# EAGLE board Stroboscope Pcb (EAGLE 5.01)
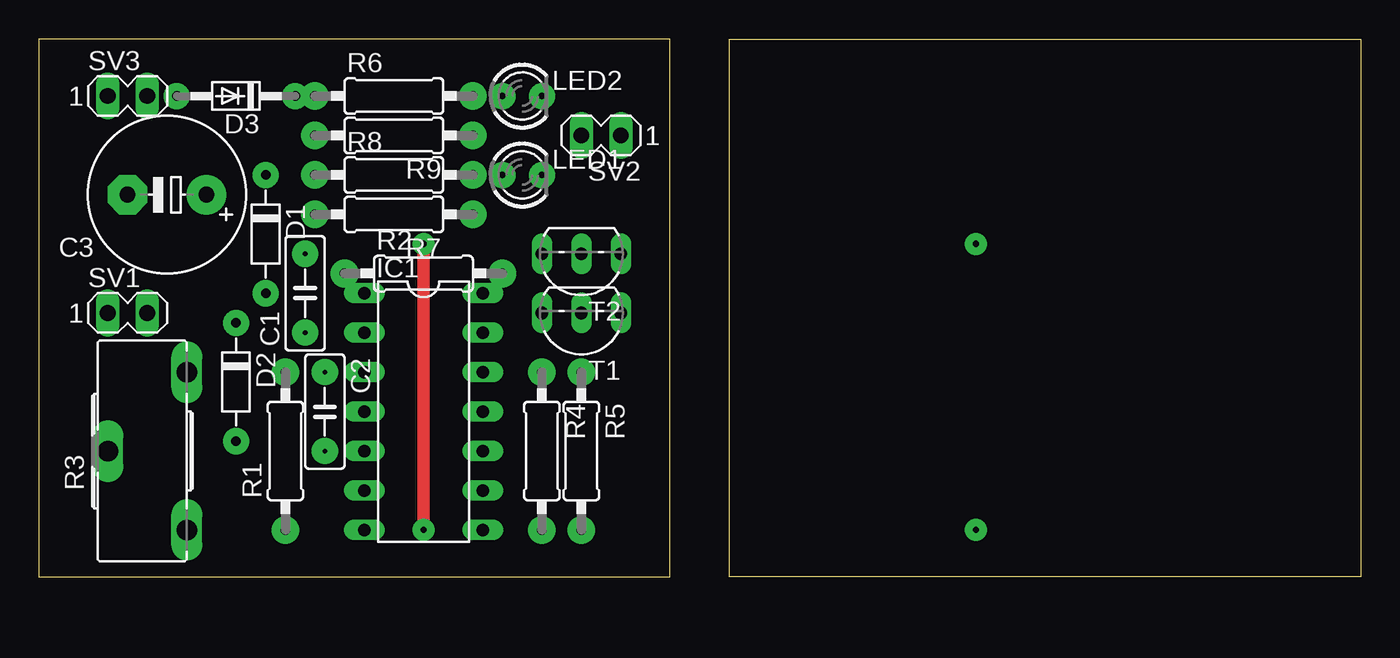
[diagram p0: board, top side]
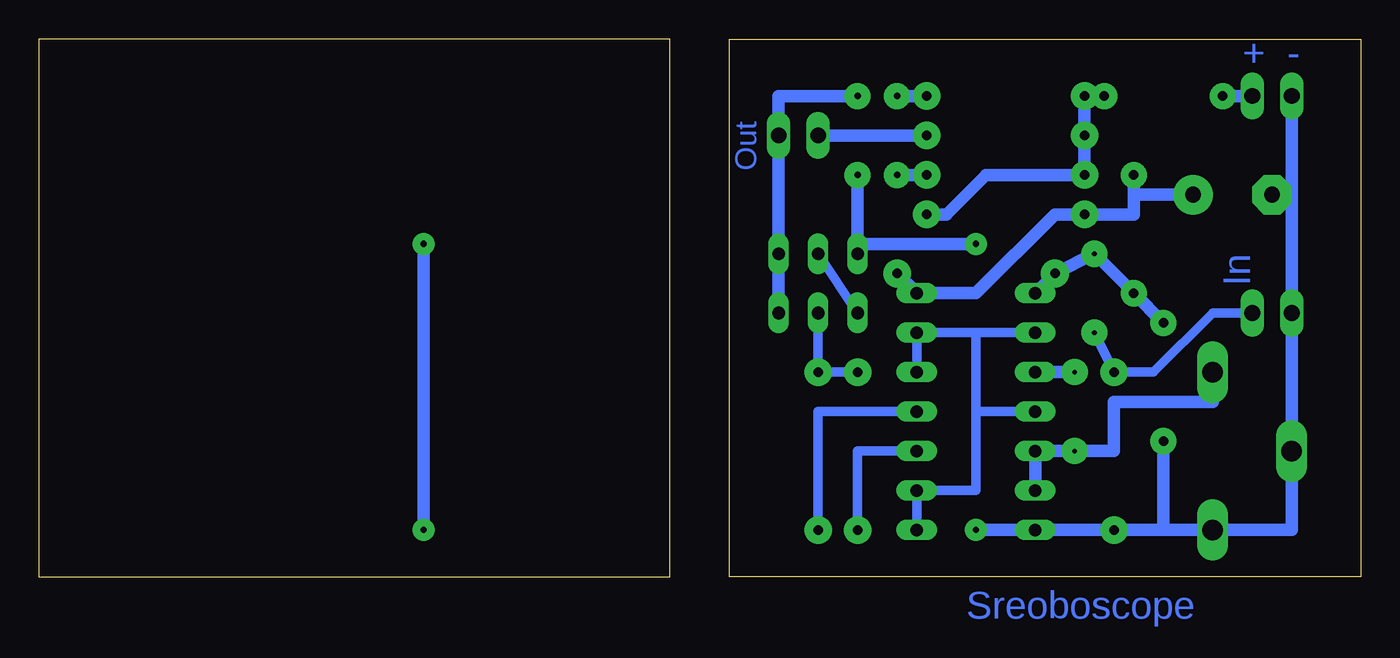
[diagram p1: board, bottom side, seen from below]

Size 85.08 x 34.59 mm. Coordinates in mm from the lower left corner, seen from the top.
Outline: 0,0 40.62,0 40.62,34.59 0,34.59 0,0
Outline: 85.08,0 44.46,0 44.46,34.59 85.08,34.59 85.08,0
Copper layers (1*16): Top 0.035mm / dielectric 1.5mm / Bottom 0.035mm
Design rules "default": minimum track width 10mil, minimum drill 24mil, track to track 8mil, track to pad 8mil, pad to pad 8mil, via to via 8mil, smd to smd 8mil, copper to edge 40mil, drill to drill 8mil, minimum pad ring 10mil, minimum via ring 8mil, stop-mask expansion 4mil, vias tented up to drill 0mil, thermal gap 10mil

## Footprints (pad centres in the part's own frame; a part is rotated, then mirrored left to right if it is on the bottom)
C050-025X075 = drill 0.305 pad 1.676 round: P$1 -2.54,0; P$2 2.54,0
E5-10,5 = drill 1.016 pad 2.54 round: + -2.54,0 | drill 1.016 pad 2.54 octagon: - 2.54,0
D-7,5/R = drill 0.61 pad 1.676 round: A 3.81,0; C -3.81,0
DO34-7/R = drill 0.61 pad 1.676 round: A 3.81,0; C -3.81,0
DIL14 = drill 0.813 long: 1 -7.62,-3.81; 2 -5.08,-3.81; 3 -2.54,-3.81; 4 0,-3.81; 5 2.54,-3.81; 6 5.08,-3.81; 7 7.62,-3.81; 8 7.62,3.81; 9 5.08,3.81; 10 2.54,3.81; 11 0,3.81; 12 -2.54,3.81; 13 -5.08,3.81; 14 -7.62,3.81
LED3MM = drill 0.406 pad 1.676 round: A -1.27,0; K 1.27,0
0207/10 = drill 0.61 pad 1.778 round: 1 -5.08,0; 2 5.08,0
CA14H = drill 1.321 long: A -5.08,0; E 5.08,0; S 0,5.08
MA2-1 = drill 1.016 long: 1 0,0; 2 2.54,0
TO92- = drill 0.813 long: 1 2.54,-1.27; 2 0,-1.27; 3 -2.54,-1.27

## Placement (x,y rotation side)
C1  100p  [C050-025X075]  17.14,18.25 90 top
C2  15n  [C050-025X075]  18.41,10.63 270 top
C3  [E5-10,5]  8.25,24.6 180 top
D1  1N4148-34/7-R  [D-7,5/R]  14.6,22.06 270 top
D2  1N4148-34/7-R  [D-7,5/R]  12.7,12.54 270 top
D3  [DO34-7/R]  12.7,30.95 180 top
IC1  4011N  [DIL14]  24.76,10.63 270 top
LED1  [LED3MM]  31.11,25.87 0 top
LED2  [LED3MM]  31.11,30.95 0 top
R1  1K  [0207/10]  15.87,8.09 90 top
R2  10M  [0207/10]  24.76,19.52 0 top
R3  47K  [CA14H]  9.52,8.09 90 top
R4  2,2K  [0207/10]  32.38,8.09 270 top
R5  2,2K  [0207/10]  34.92,8.09 270 top
R6  680  [0207/10]  22.86,30.95 0 top
R7  120  [0207/10]  22.86,23.33 180 top
R8  680  [0207/10]  22.86,25.87 0 top
R9  120  [0207/10]  22.86,28.41 180 top
SV1  [MA2-1]  4.44,16.98 0 top
SV2  [MA2-1]  37.46,28.41 180 top
SV3  [MA2-1]  4.44,30.95 0 top
T1  BC337  [TO92-]  34.92,15.71 180 top
T2  BC337  [TO92-]  34.92,19.52 180 top

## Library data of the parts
C1 C2 D1-D3 LED1 LED2 R1 R2 R4-R9 SV1-SV3 T1 T2 = 2gab
C3 = rcl
IC1 = 40xx
R3 = pot

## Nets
GND: C3.- D2.A IC1.7 LED1.K R1.1 R3.A R3.S SV1.1 SV3.1 T2.1
N$1: C1.P$1 R1.2 SV1.2
N$2: C1.P$2 D1.A D2.C IC1.1 R2.1
N$4: C2.P$1 IC1.3
N$5: C2.P$2 IC1.5 IC1.6 R3.E
N$8: IC1.2 IC1.4 IC1.8 IC1.9 IC1.12 IC1.13
N$9: T1.1 T2.2
N$10: LED2.A R6.2
N$11: LED2.K SV2.1 T1.3 T2.3
N$12: IC1.10 R4.2
N$13: IC1.11 R5.2
N$14: R4.1 R5.1 T1.2
N$15: LED1.A R8.2
N$16: R9.1 SV2.2
N$17: D3.A SV3.2
N$18: D3.C R6.1 R7.1 R8.1 R9.2
VCC: C3.+ D1.C IC1.14 R2.2 R7.2

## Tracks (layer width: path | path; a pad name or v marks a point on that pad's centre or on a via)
GND  (via drill 0.41 pad 1.42)
  Top 0.813: v24.76,3.01 v24.76,21.43
  Bottom 0.813: 4.44,24.6 SV3.1 | 4.44,24.6 C3.- | 12.06,3.01 R3.A 4.44,3.01 R3.S SV1.1 4.44,24.6 | 12.06,3.01 R1.1 IC1.7 v24.76,3.01 | D2.A 12.7,3.01 12.06,3.01 | v24.76,21.43 32.38,21.43 T2.1 LED1.K
GND1  (via drill 0.41 pad 1.42)
  Bottom 0.813: v60.32,3.01 v60.32,21.43
N$1
  Bottom 0.61: SV1.2 9.52,16.98 13.33,13.17 R1.2 C1.P$1
N$2
  Bottom 0.813: IC1.1 R2.1 C1.P$2 D1.A D2.C
N$4
  Bottom 0.813: C2.P$1 IC1.3
N$5
  Bottom 0.813: IC1.6 IC1.5 C2.P$2 15.87,8.09 15.87,11.27 9.52,11.27 R3.E
N$8
  Bottom 0.61: 24.76,10.63 IC1.4 | IC1.8 IC1.9 24.76,5.55 24.76,10.63 | IC1.12 IC1.13 24.76,15.71 | 24.76,15.71 IC1.2 | 24.76,10.63 24.76,15.71
N$9
  Bottom 0.61: T1.1 T2.2
N$10
  Bottom 0.813: R6.2 LED2.A
N$11
  Bottom 0.813: LED2.K 37.46,30.95 SV2.1 T2.3 T1.3
N$12
  Bottom 0.61: IC1.10 32.38,8.09 R4.2
N$13
  Bottom 0.61: IC1.11 34.92,10.63 R5.2
N$14
  Bottom 0.61: T1.2 R5.1 R4.1
N$15
  Bottom 0.813: R8.2 LED1.A
N$16
  Bottom 0.813: R9.1 SV2.2
N$17
  Bottom 0.813: SV3.2 D3.A
N$18
  Bottom 0.813: D3.C R6.1 R9.2 R8.1 24.12,25.87 26.66,23.33 R7.1
VCC
  Bottom 0.813: C3.+ 14.6,24.6 | 14.6,24.6 D1.C | 14.6,24.6 14.6,23.33 R7.2 19.68,23.33 24.76,18.25 IC1.14 R2.2

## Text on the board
Bottom: + - | Out | In | Sreoboscope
